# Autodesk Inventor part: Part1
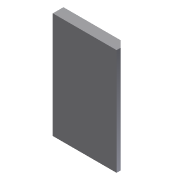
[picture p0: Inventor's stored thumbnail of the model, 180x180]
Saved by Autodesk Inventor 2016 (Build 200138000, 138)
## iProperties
Shininess: 64.0
Length Units: 11269
Angle Units: 11279
Time Units: 11290
Mass Units: 11283
Length Display Precision: 3
Angle Display Precision: 2
Compacted: True
Part Number: Part1
Document SubType Name: Modeling
Created: 2003-01
Designer: Owner
Density: 1 g/cm^3
Material: Generic
Appearance: Default
Density: 0.0
Volumn: 0.0
Area: 0.0
PropertySet Name: Model Information
Control State: 0
Master: False
Checked Out: False
Author: Owner
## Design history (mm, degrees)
sketch "Sketch1"
  geometry: L1 (-18.987, 24.241)-(11.013, 24.241); L2 (11.013, 24.241)-(11.013, -25.759); L3 (11.013, -25.759)-(-18.987, -25.759); L4 (-18.987, -25.759)-(-18.987, 24.241)
  constraints: 8 end point, 2 parallel, 1 horizontal, 1 perpendicular
  dimensions: "d0" = 30 distance of L1.start L1.end; "d1" = 50 distance of L3.end L1.start
extrude "Extrusion1" new body sketch "Sketch1" distance "d2" = 5; taper "d3" = 0 deg
chamfer "Chamfer1" distance "d4" = 3; stored, may be unused: second distance "d5" = 2, angle "d6" = 45 deg
body "Solid1"
